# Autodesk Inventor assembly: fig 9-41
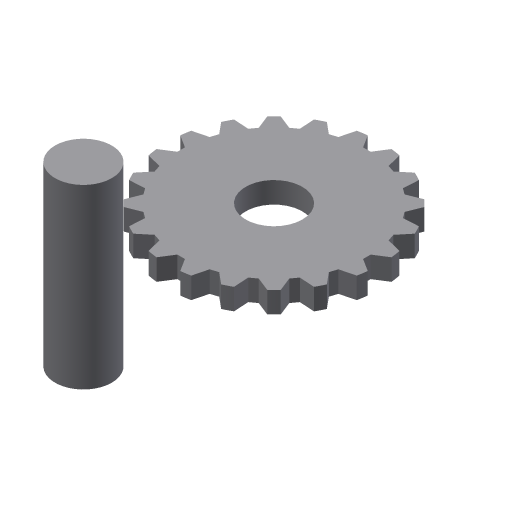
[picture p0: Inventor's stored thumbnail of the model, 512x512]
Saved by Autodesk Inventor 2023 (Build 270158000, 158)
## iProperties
Created: 2013-07
Part Number: fig 9-41
Document SubType Name: Assembly
Designer: CADCIM
Author: CADCIM
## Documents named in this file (3)
- D:\PROJECTS\Project 2022\Autodesk Inventor For Professional 2023\RESOURCES INVENTOR 2023\RESOURCES INVENTOR 2023\Inventor_2023_Part\Inventor_2023_Part\c09_Inv_2023_prt\fig 9-42.iam
- D:\PROJECTS\Project 2022\Autodesk Inventor For Professional 2023\RESOURCES INVENTOR 2023\RESOURCES INVENTOR 2023\Inventor_2023_Part\Inventor_2023_Part\c09_Inv_2023_prt\13.ipt
- D:\PROJECTS\Project 2022\Autodesk Inventor For Professional 2023\RESOURCES INVENTOR 2023\RESOURCES INVENTOR 2023\Inventor_2023_Part\Inventor_2023_Part\c09_Inv_2023_prt\14.ipt
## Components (2 placed, 2 different names)
1. 13:1
2. 14:1
